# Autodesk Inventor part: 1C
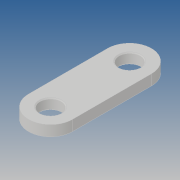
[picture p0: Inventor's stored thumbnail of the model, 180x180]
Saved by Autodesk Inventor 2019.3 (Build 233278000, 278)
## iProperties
Created: 2013-07
Part Number: 1C
Material: Ogólny
Document SubType Name: Modeling
Designer: CADENGINEERING4
Density: 1 g/cm^3
Appearance: Domyślna
Author: CADENGINEERING4
Revision Number: ÈÎºÎ
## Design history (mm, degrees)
feature "CALC-100-02-1-solid1"
node "Bryła1"
node "Bryła8"
